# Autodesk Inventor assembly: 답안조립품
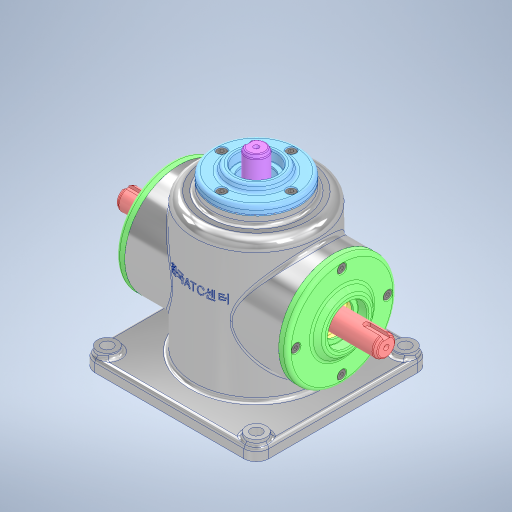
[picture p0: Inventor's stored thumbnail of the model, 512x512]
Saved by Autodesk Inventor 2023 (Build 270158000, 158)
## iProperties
Created: 2025-05
Part Number: 답안조립품
Document SubType Name: Assembly
Designer: ADMIN_PC
Author: ADMIN_PC
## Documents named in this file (13)
- C:\Users\ADMIN_PC\Desktop\750505V1008\답안조립품.iam
- C:\Users\ADMIN_PC\Desktop\750505V1008\답안본체.ipt
- C:\Users\ADMIN_PC\Desktop\750505V1008\측면 커버.ipt
- C:\Users\ADMIN_PC\Desktop\750505V1008\깊은 홈 볼 베어링 6203.ipt
- C:\Users\ADMIN_PC\Desktop\750505V1008\오일 실 17 32 8.ipt
- C:\Users\ADMIN_PC\Desktop\750505V1008\메인 축.ipt
- C:\Users\ADMIN_PC\Desktop\750505V1008\평행 키 5x5.ipt
- C:\Users\ADMIN_PC\Desktop\750505V1008\서브 베벨기어.ipt
- C:\Users\ADMIN_PC\Desktop\750505V1008\6각 구멍붙이 볼트 M4-10L.ipt
- C:\Users\ADMIN_PC\Desktop\750505V1008\윗 커버.ipt
- C:\Users\ADMIN_PC\Desktop\750505V1008\서브 축.ipt
- C:\Users\ADMIN_PC\Desktop\750505V1008\평행 키 4x4.ipt
- C:\Users\ADMIN_PC\Desktop\750505V1008\메인 베벨기어.ipt
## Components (12 placed, 1 different names)
1. 6각 구멍붙이 볼트 M4-10L:1
2. 6각 구멍붙이 볼트 M4-10L:2
3. 6각 구멍붙이 볼트 M4-10L:3
4. 6각 구멍붙이 볼트 M4-10L:4
5. 6각 구멍붙이 볼트 M4-10L:5
6. 6각 구멍붙이 볼트 M4-10L:6
7. 6각 구멍붙이 볼트 M4-10L:7
8. 6각 구멍붙이 볼트 M4-10L:8
9. 6각 구멍붙이 볼트 M4-10L:9
10. 6각 구멍붙이 볼트 M4-10L:10
11. 6각 구멍붙이 볼트 M4-10L:11
12. 6각 구멍붙이 볼트 M4-10L:12
